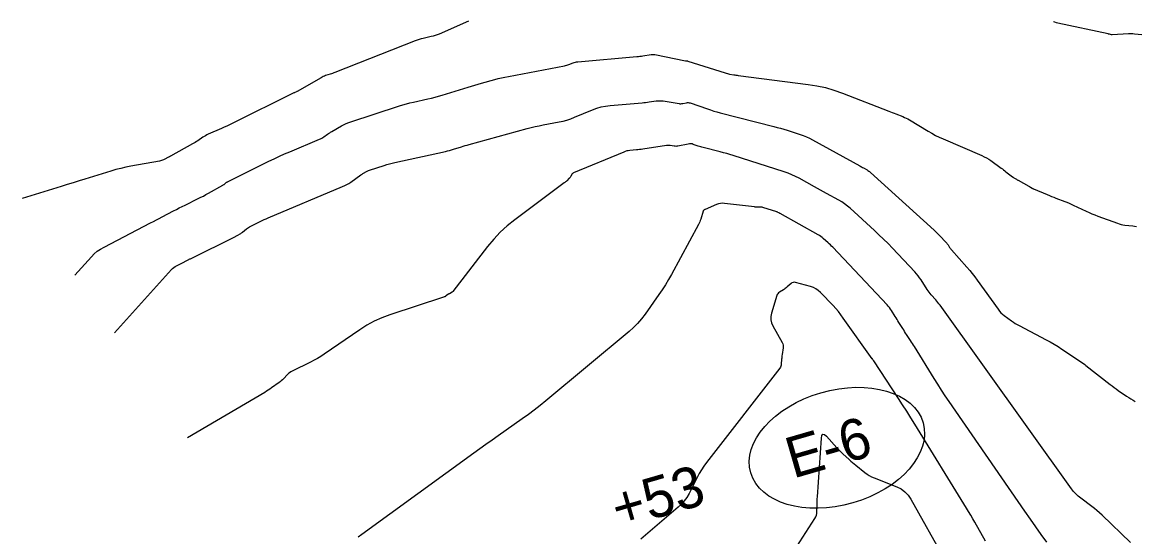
# Model space of a CAD drawing. Extents: x 1005228 to 1008882, y 1883389 to 1885754.
# Drawn here: x 1008094.4 to 1008264.2, y 1884146 to 1884224.4 of the extents above; entities that cross this region are included whole.
import ezdxf

# ---------------------------------------------------------------- set-up
doc = ezdxf.new("R2010")
doc.units = 0
for name, color, linetype in [('C-ANNO-NOTE', 7, 'Continuous'), ('R_Erosion', 7, 'Continuous'), ('S_BASELINE', 7, 'Continuous'), ('S_BRIDGE', 7, 'Continuous')]:
    doc.layers.add(name, color=color, linetype=linetype)

msp = doc.modelspace()

# ---------------------------------------------------------------- linework, layer by layer
at = {"layer": 'C-ANNO-NOTE'}
for points in [[(1008102.43, 1884185.87), (1008104.94, 1884188.66), (1008105.38, 1884189.1), (1008105.85, 1884189.5), (1008106.35, 1884189.85), (1008106.89, 1884190.16), (1008113.98, 1884193.84), (1008114.42, 1884194.07), (1008114.86, 1884194.3), (1008115.29, 1884194.52), (1008115.73, 1884194.75), (1008117.48, 1884195.66), (1008117.92, 1884195.88), (1008118.36, 1884196.11), (1008118.8, 1884196.33), (1008119.24, 1884196.55), (1008121.25, 1884197.54), (1008121.64, 1884197.74), (1008122.04, 1884197.94), (1008122.43, 1884198.15), (1008122.82, 1884198.36), (1008125, 1884199.58), (1008125.07, 1884199.62), (1008125.14, 1884199.67), (1008125.21, 1884199.71), (1008125.27, 1884199.76), (1008125.53, 1884199.98), (1008125.59, 1884200.03), (1008125.66, 1884200.07), (1008125.73, 1884200.12), (1008125.81, 1884200.16), (1008132.05, 1884203.24), (1008132.84, 1884203.62), (1008133.64, 1884204), (1008134.44, 1884204.35), (1008135.25, 1884204.7), (1008139.77, 1884206.61), (1008139.94, 1884206.68), (1008140.1, 1884206.77), (1008140.26, 1884206.86), (1008140.41, 1884206.96), (1008141.01, 1884207.38), (1008141.16, 1884207.48), (1008141.32, 1884207.58), (1008141.47, 1884207.68), (1008141.63, 1884207.77), (1008143.13, 1884208.63), (1008143.44, 1884208.8), (1008143.75, 1884208.95), (1008144.07, 1884209.08), (1008144.4, 1884209.2), (1008151.97, 1884211.68), (1008152.5, 1884211.85), (1008153.04, 1884212), (1008153.58, 1884212.14), (1008154.13, 1884212.27), (1008156.32, 1884212.75), (1008156.86, 1884212.88), (1008157.4, 1884213.02), (1008157.94, 1884213.16), (1008158.48, 1884213.32), (1008162.46, 1884214.56), (1008162.97, 1884214.71), (1008163.48, 1884214.86), (1008163.99, 1884215.01), (1008164.5, 1884215.15), (1008166.54, 1884215.72), (1008167.05, 1884215.85), (1008167.56, 1884215.97), (1008168.08, 1884216.09), (1008168.6, 1884216.19), (1008177.16, 1884217.79), (1008177.34, 1884217.83), (1008177.51, 1884217.88), (1008177.68, 1884217.93), (1008177.84, 1884217.99), (1008178.5, 1884218.27), (1008178.66, 1884218.33), (1008178.83, 1884218.38), (1008179, 1884218.41), (1008179.18, 1884218.43), (1008188.23, 1884219.2), (1008188.46, 1884219.22), (1008188.69, 1884219.25), (1008188.91, 1884219.28), (1008189.14, 1884219.31), (1008190.42, 1884219.5), (1008190.47, 1884219.51), (1008190.51, 1884219.52), (1008190.56, 1884219.52), (1008190.6, 1884219.52), (1008190.79, 1884219.53), (1008190.83, 1884219.53), (1008190.88, 1884219.53), (1008190.92, 1884219.52), (1008190.97, 1884219.52), (1008195.65, 1884218.58), (1008195.68, 1884218.57), (1008195.71, 1884218.57), (1008195.74, 1884218.57), (1008195.77, 1884218.56), (1008195.88, 1884218.56), (1008195.91, 1884218.55), (1008195.94, 1884218.55), (1008195.96, 1884218.54), (1008195.99, 1884218.53), (1008201.71, 1884216.72), (1008201.87, 1884216.67), (1008202.03, 1884216.63), (1008202.19, 1884216.59), (1008202.36, 1884216.55), (1008203.02, 1884216.43), (1008203.19, 1884216.4), (1008203.35, 1884216.37), (1008203.52, 1884216.35), (1008203.69, 1884216.32), (1008214.35, 1884214.97), (1008215.69, 1884214.76), (1008217.01, 1884214.47), (1008218.31, 1884214.1), (1008219.59, 1884213.64), (1008226.67, 1884210.9), (1008226.94, 1884210.8), (1008227.21, 1884210.69), (1008227.48, 1884210.58), (1008227.75, 1884210.48), (1008228.82, 1884210.06), (1008229.09, 1884209.94), (1008229.35, 1884209.82), (1008229.6, 1884209.69), (1008229.85, 1884209.54), (1008232.68, 1884207.82), (1008233.24, 1884207.5), (1008233.81, 1884207.19), (1008234.39, 1884206.91), (1008234.98, 1884206.64), (1008240.88, 1884204.11), (1008241.24, 1884203.94), (1008241.59, 1884203.76), (1008241.93, 1884203.55), (1008242.26, 1884203.33), (1008243.84, 1884202.19), (1008244.02, 1884202.06), (1008244.2, 1884201.93), (1008244.38, 1884201.79), (1008244.55, 1884201.65), (1008245.58, 1884200.84), (1008245.6, 1884200.83), (1008245.61, 1884200.82), (1008245.62, 1884200.81), (1008245.64, 1884200.8), (1008245.69, 1884200.77), (1008245.7, 1884200.76), (1008245.72, 1884200.75), (1008245.73, 1884200.74), (1008245.75, 1884200.73), (1008246.15, 1884200.49), (1008246.22, 1884200.45), (1008246.3, 1884200.41), (1008246.37, 1884200.37), (1008246.44, 1884200.33), (1008248.04, 1884199.44), (1008248.11, 1884199.4), (1008248.17, 1884199.37), (1008248.23, 1884199.33), (1008248.29, 1884199.29), (1008248.54, 1884199.14), (1008248.6, 1884199.1), (1008248.66, 1884199.07), (1008248.73, 1884199.04), (1008248.79, 1884199.01), (1008250.88, 1884198.15), (1008251.21, 1884198.02), (1008251.54, 1884197.88), (1008251.87, 1884197.75), (1008252.2, 1884197.62), (1008253.53, 1884197.11), (1008253.86, 1884196.98), (1008254.19, 1884196.84), (1008254.52, 1884196.69), (1008254.84, 1884196.55), (1008256.81, 1884195.62), (1008257.25, 1884195.42), (1008257.69, 1884195.23), (1008258.13, 1884195.05), (1008258.58, 1884194.87), (1008261.57, 1884193.78), (1008261.85, 1884193.69), (1008262.13, 1884193.61), (1008262.42, 1884193.55), (1008262.71, 1884193.51), (1008263.94, 1884193.38), (1008264.21, 1884193.34), (1008264.47, 1884193.29)], [(1008108.49, 1884177.07), (1008117.18, 1884186.71), (1008117.35, 1884186.88), (1008117.53, 1884187.04), (1008117.73, 1884187.17), (1008117.93, 1884187.29), (1008119.05, 1884187.87), (1008119.14, 1884187.92), (1008119.22, 1884187.96), (1008119.3, 1884188), (1008119.39, 1884188.05), (1008119.72, 1884188.22), (1008119.8, 1884188.26), (1008119.88, 1884188.3), (1008119.97, 1884188.34), (1008120.05, 1884188.38), (1008126.92, 1884191.77), (1008127.01, 1884191.82), (1008127.11, 1884191.87), (1008127.2, 1884191.92), (1008127.3, 1884191.98), (1008127.68, 1884192.19), (1008127.77, 1884192.24), (1008127.86, 1884192.3), (1008127.95, 1884192.36), (1008128.03, 1884192.43), (1008128.64, 1884192.93), (1008128.78, 1884193.03), (1008128.91, 1884193.13), (1008129.06, 1884193.22), (1008129.2, 1884193.29), (1008130.72, 1884194.04), (1008131.02, 1884194.19), (1008131.33, 1884194.33), (1008131.64, 1884194.47), (1008131.95, 1884194.6), (1008143.28, 1884199.38), (1008143.61, 1884199.52), (1008143.92, 1884199.69), (1008144.23, 1884199.87), (1008144.53, 1884200.06), (1008146.08, 1884201.15), (1008146.18, 1884201.22), (1008146.29, 1884201.29), (1008146.39, 1884201.35), (1008146.5, 1884201.41), (1008146.93, 1884201.66), (1008147.04, 1884201.72), (1008147.15, 1884201.77), (1008147.26, 1884201.82), (1008147.38, 1884201.86), (1008149.62, 1884202.6), (1008150.03, 1884202.73), (1008150.45, 1884202.85), (1008150.87, 1884202.96), (1008151.29, 1884203.05), (1008159.02, 1884204.75), (1008159.32, 1884204.82), (1008159.63, 1884204.9), (1008159.93, 1884204.98), (1008160.23, 1884205.07), (1008161.42, 1884205.44), (1008161.72, 1884205.53), (1008162.02, 1884205.62), (1008162.32, 1884205.71), (1008162.62, 1884205.79), (1008171.47, 1884208.23), (1008172.07, 1884208.39), (1008172.67, 1884208.53), (1008173.28, 1884208.66), (1008173.89, 1884208.79), (1008176.34, 1884209.24), (1008176.95, 1884209.37), (1008177.54, 1884209.53), (1008178.13, 1884209.73), (1008178.71, 1884209.95), (1008181.45, 1884211.09), (1008182.1, 1884211.33), (1008182.77, 1884211.52), (1008183.45, 1884211.66), (1008184.14, 1884211.74), (1008189.02, 1884212.16), (1008189.29, 1884212.18), (1008189.56, 1884212.21), (1008189.83, 1884212.24), (1008190.1, 1884212.28), (1008191.17, 1884212.44), (1008191.44, 1884212.47), (1008191.71, 1884212.48), (1008191.98, 1884212.47), (1008192.24, 1884212.44), (1008194.66, 1884212.04), (1008194.8, 1884212.02), (1008194.94, 1884212.02), (1008195.08, 1884212.03), (1008195.22, 1884212.05), (1008195.79, 1884212.17), (1008195.93, 1884212.19), (1008196.07, 1884212.19), (1008196.2, 1884212.17), (1008196.34, 1884212.13), (1008198.98, 1884211.22), (1008199.47, 1884211.06), (1008199.96, 1884210.9), (1008200.45, 1884210.76), (1008200.94, 1884210.63), (1008209.13, 1884208.54), (1008209.64, 1884208.41), (1008210.14, 1884208.27), (1008210.64, 1884208.12), (1008211.14, 1884207.97), (1008213.13, 1884207.33), (1008213.62, 1884207.16), (1008214.11, 1884206.97), (1008214.58, 1884206.75), (1008215.04, 1884206.51), (1008222.26, 1884202.52), (1008222.4, 1884202.45), (1008222.53, 1884202.37), (1008222.67, 1884202.3), (1008222.81, 1884202.22), (1008223.35, 1884201.92), (1008223.49, 1884201.84), (1008223.62, 1884201.75), (1008223.74, 1884201.66), (1008223.86, 1884201.55), (1008233.62, 1884192.71), (1008233.82, 1884192.52), (1008234.03, 1884192.32), (1008234.23, 1884192.12), (1008234.43, 1884191.91), (1008235.45, 1884190.83), (1008235.52, 1884190.75), (1008235.59, 1884190.66), (1008235.66, 1884190.57), (1008235.72, 1884190.48), (1008235.96, 1884190.1), (1008236.02, 1884190.01), (1008236.09, 1884189.92), (1008236.16, 1884189.83), (1008236.23, 1884189.75), (1008238.61, 1884187.07), (1008239.03, 1884186.59), (1008239.43, 1884186.1), (1008239.82, 1884185.6), (1008240.19, 1884185.09), (1008243.37, 1884180.66), (1008243.58, 1884180.39), (1008243.8, 1884180.14), (1008244.05, 1884179.91), (1008244.31, 1884179.7), (1008245.41, 1884178.89), (1008245.69, 1884178.69), (1008245.97, 1884178.5), (1008246.26, 1884178.33), (1008246.56, 1884178.17), (1008250.7, 1884176.01), (1008251.31, 1884175.68), (1008251.92, 1884175.33), (1008252.52, 1884174.97), (1008253.11, 1884174.58), (1008256.57, 1884172.27), (1008256.58, 1884172.26), (1008256.6, 1884172.24), (1008256.62, 1884172.23), (1008256.63, 1884172.21), (1008256.7, 1884172.15), (1008256.71, 1884172.13), (1008256.73, 1884172.11), (1008256.75, 1884172.1), (1008256.77, 1884172.08), (1008260.45, 1884169.21), (1008260.76, 1884168.98), (1008261.07, 1884168.74), (1008261.39, 1884168.52), (1008261.7, 1884168.29), (1008262.98, 1884167.4), (1008263.3, 1884167.19), (1008263.63, 1884166.98), (1008263.96, 1884166.79), (1008264.31, 1884166.61)], [(1008263.57, 1884145.06), (1008259.23, 1884149.26), (1008258.85, 1884149.61), (1008258.46, 1884149.95), (1008258.06, 1884150.28), (1008257.65, 1884150.59), (1008255.99, 1884151.83), (1008255.59, 1884152.15), (1008255.21, 1884152.5), (1008254.87, 1884152.88), (1008254.55, 1884153.28), (1008234.5, 1884181.27), (1008234.34, 1884181.48), (1008234.18, 1884181.69), (1008234.02, 1884181.89), (1008233.85, 1884182.08), (1008233.16, 1884182.86), (1008232.99, 1884183.05), (1008232.83, 1884183.26), (1008232.68, 1884183.46), (1008232.54, 1884183.68), (1008231.6, 1884185.16), (1008231.39, 1884185.47), (1008231.16, 1884185.78), (1008230.93, 1884186.07), (1008230.67, 1884186.35), (1008227.23, 1884190), (1008226.56, 1884190.69), (1008225.88, 1884191.37), (1008225.18, 1884192.04), (1008224.48, 1884192.7), (1008220.76, 1884196.07), (1008220.36, 1884196.41), (1008219.94, 1884196.73), (1008219.5, 1884197.03), (1008219.05, 1884197.3), (1008217.19, 1884198.32), (1008216.73, 1884198.58), (1008216.27, 1884198.84), (1008215.8, 1884199.1), (1008215.34, 1884199.35), (1008213, 1884200.65), (1008212.44, 1884200.93), (1008211.88, 1884201.19), (1008211.31, 1884201.42), (1008210.72, 1884201.63), (1008202.91, 1884204.11), (1008202.42, 1884204.26), (1008201.93, 1884204.41), (1008201.43, 1884204.54), (1008200.94, 1884204.67), (1008198.35, 1884205.34), (1008198.16, 1884205.39), (1008197.97, 1884205.44), (1008197.78, 1884205.5), (1008197.59, 1884205.56), (1008196.83, 1884205.82), (1008196.64, 1884205.88), (1008196.45, 1884205.9), (1008196.26, 1884205.9), (1008196.06, 1884205.87), (1008194.46, 1884205.54), (1008194.32, 1884205.52), (1008194.18, 1884205.51), (1008194.04, 1884205.52), (1008193.89, 1884205.53), (1008193.32, 1884205.63), (1008193.18, 1884205.65), (1008193.03, 1884205.65), (1008192.89, 1884205.65), (1008192.75, 1884205.63), (1008189.11, 1884205.08), (1008188.87, 1884205.05), (1008188.62, 1884205.02), (1008188.38, 1884204.99), (1008188.14, 1884204.97), (1008187.16, 1884204.88), (1008186.91, 1884204.85), (1008186.68, 1884204.81), (1008186.44, 1884204.74), (1008186.21, 1884204.65), (1008178.56, 1884201.48), (1008178.48, 1884201.44), (1008178.41, 1884201.39), (1008178.35, 1884201.33), (1008178.3, 1884201.25), (1008178.12, 1884200.93), (1008178.07, 1884200.86), (1008178.02, 1884200.78), (1008177.96, 1884200.71), (1008177.9, 1884200.65), (1008177.51, 1884200.26), (1008177.42, 1884200.17), (1008177.32, 1884200.09), (1008177.23, 1884200.01), (1008177.13, 1884199.94), (1008169.57, 1884194.3), (1008168.43, 1884193.39), (1008167.36, 1884192.41), (1008166.36, 1884191.35), (1008165.43, 1884190.23), (1008160.13, 1884183.38), (1008160.09, 1884183.33), (1008160.04, 1884183.28), (1008159.99, 1884183.25), (1008159.93, 1884183.21), (1008159.7, 1884183.09), (1008159.64, 1884183.06), (1008159.59, 1884183.03), (1008159.53, 1884183), (1008159.48, 1884182.96), (1008159.07, 1884182.69), (1008158.98, 1884182.63), (1008158.89, 1884182.58), (1008158.79, 1884182.54), (1008158.7, 1884182.5), (1008150.5, 1884179.8), (1008149.29, 1884179.36), (1008148.12, 1884178.83), (1008146.99, 1884178.22), (1008145.91, 1884177.53), (1008140.49, 1884173.81), (1008139.99, 1884173.48), (1008139.48, 1884173.17), (1008138.95, 1884172.88), (1008138.41, 1884172.61), (1008135.57, 1884171.22), (1008135.37, 1884171.11), (1008135.19, 1884170.99), (1008135.02, 1884170.86), (1008134.86, 1884170.7), (1008134.25, 1884170.06), (1008134.1, 1884169.9), (1008133.93, 1884169.75), (1008133.76, 1884169.61), (1008133.59, 1884169.47), (1008132.46, 1884168.66), (1008132.21, 1884168.49), (1008131.95, 1884168.32), (1008131.7, 1884168.15), (1008131.43, 1884167.99), (1008119.63, 1884161.06)], [(1008250.79, 1884145.15), (1008249.95, 1884146.32), (1008249.12, 1884147.49), (1008248.29, 1884148.66), (1008247.47, 1884149.84), (1008235.87, 1884166.61), (1008235.28, 1884167.47), (1008234.71, 1884168.34), (1008234.14, 1884169.22), (1008233.59, 1884170.11), (1008230.58, 1884174.97), (1008230.44, 1884175.2), (1008230.29, 1884175.43), (1008230.14, 1884175.66), (1008229.99, 1884175.89), (1008229.39, 1884176.81), (1008229.24, 1884177.04), (1008229.09, 1884177.27), (1008228.95, 1884177.5), (1008228.8, 1884177.73), (1008228.22, 1884178.66), (1008228.08, 1884178.89), (1008227.93, 1884179.12), (1008227.79, 1884179.34), (1008227.65, 1884179.57), (1008227.07, 1884180.48), (1008226.92, 1884180.7), (1008226.76, 1884180.91), (1008226.59, 1884181.12), (1008226.41, 1884181.32), (1008218.11, 1884190.12), (1008217.94, 1884190.3), (1008217.76, 1884190.47), (1008217.59, 1884190.64), (1008217.41, 1884190.81), (1008216.68, 1884191.47), (1008216.49, 1884191.63), (1008216.3, 1884191.77), (1008216.1, 1884191.91), (1008215.89, 1884192.04), (1008210.08, 1884195.26), (1008210.04, 1884195.29), (1008210, 1884195.31), (1008209.96, 1884195.33), (1008209.92, 1884195.35), (1008209.76, 1884195.44), (1008209.72, 1884195.46), (1008209.68, 1884195.48), (1008209.64, 1884195.49), (1008209.6, 1884195.51), (1008207.45, 1884196.19), (1008207.35, 1884196.22), (1008207.24, 1884196.24), (1008207.13, 1884196.25), (1008207.02, 1884196.25), (1008206.58, 1884196.25), (1008206.47, 1884196.25), (1008206.36, 1884196.25), (1008206.26, 1884196.26), (1008206.15, 1884196.27), (1008201.62, 1884196.81), (1008201.29, 1884196.83), (1008200.98, 1884196.8), (1008200.67, 1884196.73), (1008200.37, 1884196.63), (1008198.63, 1884195.87), (1008198.6, 1884195.86), (1008198.57, 1884195.84), (1008198.54, 1884195.83), (1008198.51, 1884195.81), (1008198.39, 1884195.74), (1008198.37, 1884195.72), (1008198.34, 1884195.7), (1008198.33, 1884195.67), (1008198.32, 1884195.64), (1008197.96, 1884194.43), (1008197.89, 1884194.22), (1008197.81, 1884194.01), (1008197.72, 1884193.81), (1008197.62, 1884193.61), (1008193.51, 1884185.98), (1008193.06, 1884185.19), (1008192.59, 1884184.41), (1008192.1, 1884183.64), (1008191.59, 1884182.89), (1008189.47, 1884179.92), (1008188.93, 1884179.2), (1008188.33, 1884178.51), (1008187.7, 1884177.87), (1008187.02, 1884177.27), (1008174.32, 1884166.68), (1008173.44, 1884165.97), (1008172.55, 1884165.27), (1008171.65, 1884164.59), (1008170.73, 1884163.93), (1008167.03, 1884161.33), (1008166.11, 1884160.68), (1008165.18, 1884160.02), (1008164.26, 1884159.36), (1008163.35, 1884158.7), (1008146.23, 1884146.3), (1008145.68, 1884145.91)], [(1008209.88, 1884140.19), (1008215.4, 1884148.74), (1008215.54, 1884148.98), (1008215.63, 1884149.24), (1008215.69, 1884149.5), (1008215.71, 1884149.78), (1008215.72, 1884150.91), (1008215.73, 1884151.19), (1008215.74, 1884151.48), (1008215.75, 1884151.76), (1008215.77, 1884152.04), (1008216.39, 1884161.02), (1008216.47, 1884161.42), (1008216.62, 1884161.6), (1008216.84, 1884161.55), (1008217.15, 1884161.29), (1008218.76, 1884159.53), (1008218.98, 1884159.29), (1008219.21, 1884159.06), (1008219.44, 1884158.83), (1008219.68, 1884158.61), (1008220.64, 1884157.72), (1008220.88, 1884157.5), (1008221.12, 1884157.28), (1008221.37, 1884157.07), (1008221.63, 1884156.87), (1008223.02, 1884155.75), (1008223.35, 1884155.51), (1008223.69, 1884155.3), (1008224.05, 1884155.11), (1008224.42, 1884154.95), (1008227.9, 1884153.57), (1008228.57, 1884153.25), (1008229.15, 1884152.82), (1008229.64, 1884152.3), (1008230.06, 1884151.69), (1008235.17, 1884142.55)]]:
    msp.add_lwpolyline(points, dxfattribs=at)
at = {"layer": 'R_Erosion'}
msp.add_ellipse((1008218.76, 1884159.53), major_axis=(13.16, 3.81), ratio=0.638788, dxfattribs=at)
at = {"layer": 'S_BRIDGE'}
for points in [[(1008162.5, 1884224.6), (1008158.03, 1884222.65), (1008157.74, 1884222.53), (1008157.44, 1884222.43), (1008157.14, 1884222.33), (1008156.83, 1884222.26), (1008155.6, 1884221.97), (1008155.29, 1884221.89), (1008154.99, 1884221.8), (1008154.69, 1884221.7), (1008154.39, 1884221.59), (1008142.11, 1884216.79), (1008141.94, 1884216.72), (1008141.76, 1884216.65), (1008141.58, 1884216.59), (1008141.4, 1884216.53), (1008140.69, 1884216.3), (1008140.51, 1884216.23), (1008140.34, 1884216.16), (1008140.17, 1884216.08), (1008140, 1884215.99), (1008136.36, 1884213.9), (1008136.35, 1884213.89), (1008136.34, 1884213.89), (1008136.34, 1884213.88), (1008136.33, 1884213.88), (1008136.3, 1884213.85), (1008136.29, 1884213.85), (1008136.28, 1884213.84), (1008136.27, 1884213.84), (1008136.26, 1884213.84), (1008136.02, 1884213.73), (1008135.98, 1884213.72), (1008135.93, 1884213.7), (1008135.89, 1884213.68), (1008135.85, 1884213.66), (1008126.41, 1884208.99), (1008126.01, 1884208.8), (1008125.61, 1884208.61), (1008125.2, 1884208.42), (1008124.8, 1884208.24), (1008122.78, 1884207.35), (1008122.57, 1884207.25), (1008122.36, 1884207.14), (1008122.15, 1884207.03), (1008121.96, 1884206.9), (1008121.17, 1884206.38), (1008120.98, 1884206.25), (1008120.78, 1884206.12), (1008120.57, 1884206), (1008120.37, 1884205.88), (1008117.01, 1884204.01), (1008116.99, 1884204), (1008116.97, 1884203.99), (1008116.96, 1884203.98), (1008116.94, 1884203.97), (1008116.87, 1884203.94), (1008116.85, 1884203.93), (1008116.83, 1884203.92), (1008116.81, 1884203.91), (1008116.8, 1884203.9), (1008115.96, 1884203.47), (1008115.82, 1884203.4), (1008115.67, 1884203.34), (1008115.51, 1884203.3), (1008115.35, 1884203.26), (1008110.98, 1884202.48), (1008110.2, 1884202.33), (1008109.42, 1884202.16), (1008108.66, 1884201.96), (1008107.89, 1884201.73), (1008103.96, 1884200.52), (1008103.06, 1884200.23), (1008102.15, 1884199.95), (1008101.24, 1884199.67), (1008100.33, 1884199.39), (1008094.39, 1884197.55)], [(1008265.32, 1884222.51), (1008264.18, 1884222.63), (1008263.95, 1884222.66), (1008263.72, 1884222.67), (1008263.49, 1884222.67), (1008263.25, 1884222.66), (1008260.79, 1884222.51), (1008260.79, 1884222.51), (1008260.78, 1884222.51), (1008260.72, 1884222.52), (1008260.71, 1884222.53), (1008260.7, 1884222.53), (1008260.68, 1884222.53), (1008260.67, 1884222.53), (1008260.37, 1884222.61), (1008260.32, 1884222.62), (1008260.27, 1884222.63), (1008260.21, 1884222.65), (1008260.16, 1884222.66), (1008252.5, 1884224.32), (1008252.28, 1884224.38), (1008252.05, 1884224.44), (1008251.84, 1884224.51)], [(1008241.42, 1884145.29), (1008239.82, 1884148.16), (1008239.51, 1884148.71), (1008239.19, 1884149.25), (1008238.87, 1884149.79), (1008238.54, 1884150.33), (1008230.64, 1884163.14), (1008230.02, 1884164.12), (1008229.41, 1884165.1), (1008228.78, 1884166.07), (1008228.15, 1884167.04), (1008224.37, 1884172.79), (1008224.36, 1884172.81), (1008224.34, 1884172.84), (1008224.32, 1884172.87), (1008224.3, 1884172.89), (1008224.24, 1884173), (1008224.22, 1884173.03), (1008224.2, 1884173.06), (1008224.18, 1884173.08), (1008224.16, 1884173.11), (1008219.73, 1884179.32), (1008219.36, 1884179.82), (1008218.98, 1884180.3), (1008218.58, 1884180.77), (1008218.16, 1884181.22), (1008216.25, 1884183.24), (1008215.92, 1884183.55), (1008215.55, 1884183.8), (1008215.16, 1884184), (1008214.72, 1884184.15), (1008212.42, 1884184.76), (1008212.23, 1884184.79), (1008212.06, 1884184.77), (1008211.9, 1884184.71), (1008211.75, 1884184.6), (1008211.15, 1884184.07), (1008211.02, 1884183.95), (1008210.88, 1884183.84), (1008210.73, 1884183.74), (1008210.58, 1884183.64), (1008209.98, 1884183.27), (1008209.84, 1884183.16), (1008209.72, 1884183.04), (1008209.64, 1884182.9), (1008209.57, 1884182.74), (1008208.78, 1884180.05), (1008208.68, 1884179.55), (1008208.68, 1884179.07), (1008208.79, 1884178.59), (1008208.99, 1884178.12), (1008210.4, 1884175.61), (1008210.49, 1884175.41), (1008210.55, 1884175.2), (1008210.57, 1884174.98), (1008210.55, 1884174.76), (1008210.39, 1884173.77), (1008210.37, 1884173.58), (1008210.34, 1884173.4), (1008210.33, 1884173.22), (1008210.31, 1884173.04), (1008210.27, 1884172.31), (1008210.24, 1884172.13), (1008210.19, 1884171.97), (1008210.12, 1884171.81), (1008210.02, 1884171.66), (1008198.86, 1884157.29), (1008198.45, 1884156.74), (1008198.08, 1884156.17), (1008197.73, 1884155.59), (1008197.41, 1884154.99), (1008196.18, 1884152.56), (1008195.84, 1884151.97), (1008195.46, 1884151.43), (1008195.02, 1884150.92), (1008194.52, 1884150.46), (1008188.81, 1884145.58)]]:
    msp.add_lwpolyline(points, dxfattribs=at)

# ---------------------------------------------------------------- texts
at = {"layer": 'R_Erosion'}
msp.add_text('E-6', height=6.25, rotation=16.1588, dxfattribs=at).set_placement((1008212.05, 1884154.81))
at = {"layer": 'S_BASELINE'}
msp.add_text('+53', height=6.25, rotation=16.1588, dxfattribs=at).set_placement((1008185.43, 1884147.1))

doc.saveas('drawing.dxf')
